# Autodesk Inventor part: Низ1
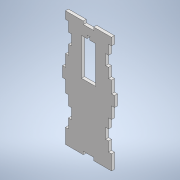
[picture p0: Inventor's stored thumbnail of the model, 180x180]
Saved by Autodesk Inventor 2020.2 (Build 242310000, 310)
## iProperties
Created: 2020-04
Part Number: Низ1
Material: Типовые
Document SubType Name: Modeling
Designer: Алексей
Density: 1 g/cm^3
Appearance: По умолчанию
Author: Алексей
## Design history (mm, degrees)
sketch "Эскиз1"
  geometry: L1 (-4, -14)-(-4, 0) reference; L2 (0, -14)-(-4, -14) reference; L3 (0, 0)-(0, -14) reference; L4 (0, 0)-(-4, 0) reference; L5 (-4, 66)-(-66, 66); L6 (-66, 66)-(-66, -90); L7 (-66, -90)-(-4, -90); L8 (-4, -90)-(-4, 66); L9 (-66, 0)-(-70, 0); L10 (-70, 0)-(-70, -14); L11 (-70, -14)-(-66, -14); L12 (-66, -14)-(-66, 0); L13 (-4, 66)-(-4, 56) reference; L14 (-4, 56)-(0, 56) reference; L15 (0, 66)-(0, 56) reference; L16 (-4, 66)-(0, 66) reference; L17 (-4, 0)-(0, 0) reference; L18 (0, 16)-(0, 0) reference; L19 (-4, 16)-(0, 16) reference; L20 (-4, 16)-(-4, 0) reference; L21 (0, -14)-(-4, -14) reference; L22 (-4, -14)-(-4, -30) reference; L23 (-4, -30)-(0, -30) reference; L24 (0, -14)-(0, -30) reference; L25 (-4, -70)-(-4, -90) reference; L26 (-4, -90)-(0, -90) reference; L27 (0, -70)-(0, -90) reference; L28 (-4, -70)-(0, -70) reference; L29 (-4, 56)-(-8, 56); L30 (-8, 56)-(-8, 16); L31 (-8, 16)-(-4, 16); L32 (-4, 16)-(-4, 56); L33 (-4, -30)-(-8, -30); L34 (-8, -30)-(-8, -70); L35 (-8, -70)-(-4, -70); L36 (-4, -70)-(-4, -30); L37 (-66, 56)-(-62, 56); L38 (-62, 56)-(-62, 16); L39 (-62, 16)-(-66, 16); L40 (-66, 16)-(-66, 56); L41 (-66, -30)-(-62, -30); L42 (-62, -30)-(-62, -70); L43 (-62, -70)-(-66, -70); L44 (-66, -70)-(-66, -30); L45 (-8, 43)-(-12, 43); L46 (-12, 43)-(-12, 29); L47 (-12, 29)-(-8, 29); L48 (-8, 29)-(-8, 43); L49 (-62, 43)-(-58, 43); L50 (-58, 43)-(-58, 29); L51 (-58, 29)-(-62, 29); L52 (-62, 29)-(-62, 43); L53 (-8, -43)-(-12, -43); L54 (-12, -43)-(-12, -57); L55 (-12, -57)-(-8, -57); L56 (-8, -57)-(-8, -43); L57 (-62, -43)-(-58, -43); L58 (-58, -43)-(-58, -57); L59 (-58, -57)-(-62, -57); L60 (-62, -57)-(-62, -43); 13 further points
  constraints: 80 end point, 20 parallel, 13 point on line, 10 collinear, 10 horizontal, 10 perpendicular, 4 midpoint, 2 other
  dimensions: "d0" = 4 distance of L11.end L10.end; "d1" = 4 distance of L30.end L31.end; "d2" = 4 distance of L38.end L39.end; "d3" = 4 distance of L47.end L46.end; "d4" = 14 distance of L46.end L45.end; "d5" = 4 distance of L50.end L51.end; "d6" = 4 distance of L55.end L54.end; "d7" = 14 distance of L54.end L53.end; "d8" = 70 distance between parallel lines of L10 L3
extrude "Выдавливание1" new body sketch "Эскиз1" distance "d9" = 4; taper "d10" = 0 deg
sketch "Эскиз2"
  geometry: L1 (-28, -90)-(-42, -90); L2 (-42, -90)-(-42, -86); L3 (-42, -86)-(-28, -86); L4 (-28, -86)-(-28, -90); L5 (-28, 62)-(-42, 62); L6 (-42, 62)-(-42, 66); L7 (-42, 66)-(-28, 66); L8 (-28, 66)-(-28, 62); L9 (-66, -90)-(-4, -90) reference; L10 (-4, 66)-(-66, 66) reference; 3 further points
  constraints: 16 end point, 4 midpoint, 4 parallel, 2 horizontal, 2 perpendicular
  dimensions: "d11" = 14 distance of L2.end L3.end; "d12" = 4 distance of L1.end L2.end; "d13" = 14 distance of L6.end L7.end; "d14" = 4 distance of L5.end L6.end
extrude "Выдавливание2" cut sketch "Эскиз2" extent not by distance; stored distance "d15" = 0; taper "d16" = 0 deg
node "Твердое тело1"
node "Ссылка1"
node "Ссылка2"
node "Ссылка3"
node "Ссылка4"
node "Ссылка5"
